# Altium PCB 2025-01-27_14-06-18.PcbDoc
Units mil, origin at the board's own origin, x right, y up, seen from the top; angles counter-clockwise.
Board outline 2000 x 2410 mil, 4 copper layers (Top Layer, MidLayer1, MidLayer2, Bottom Layer); 13 components, 6 nets, 26 pads, 90 vias.
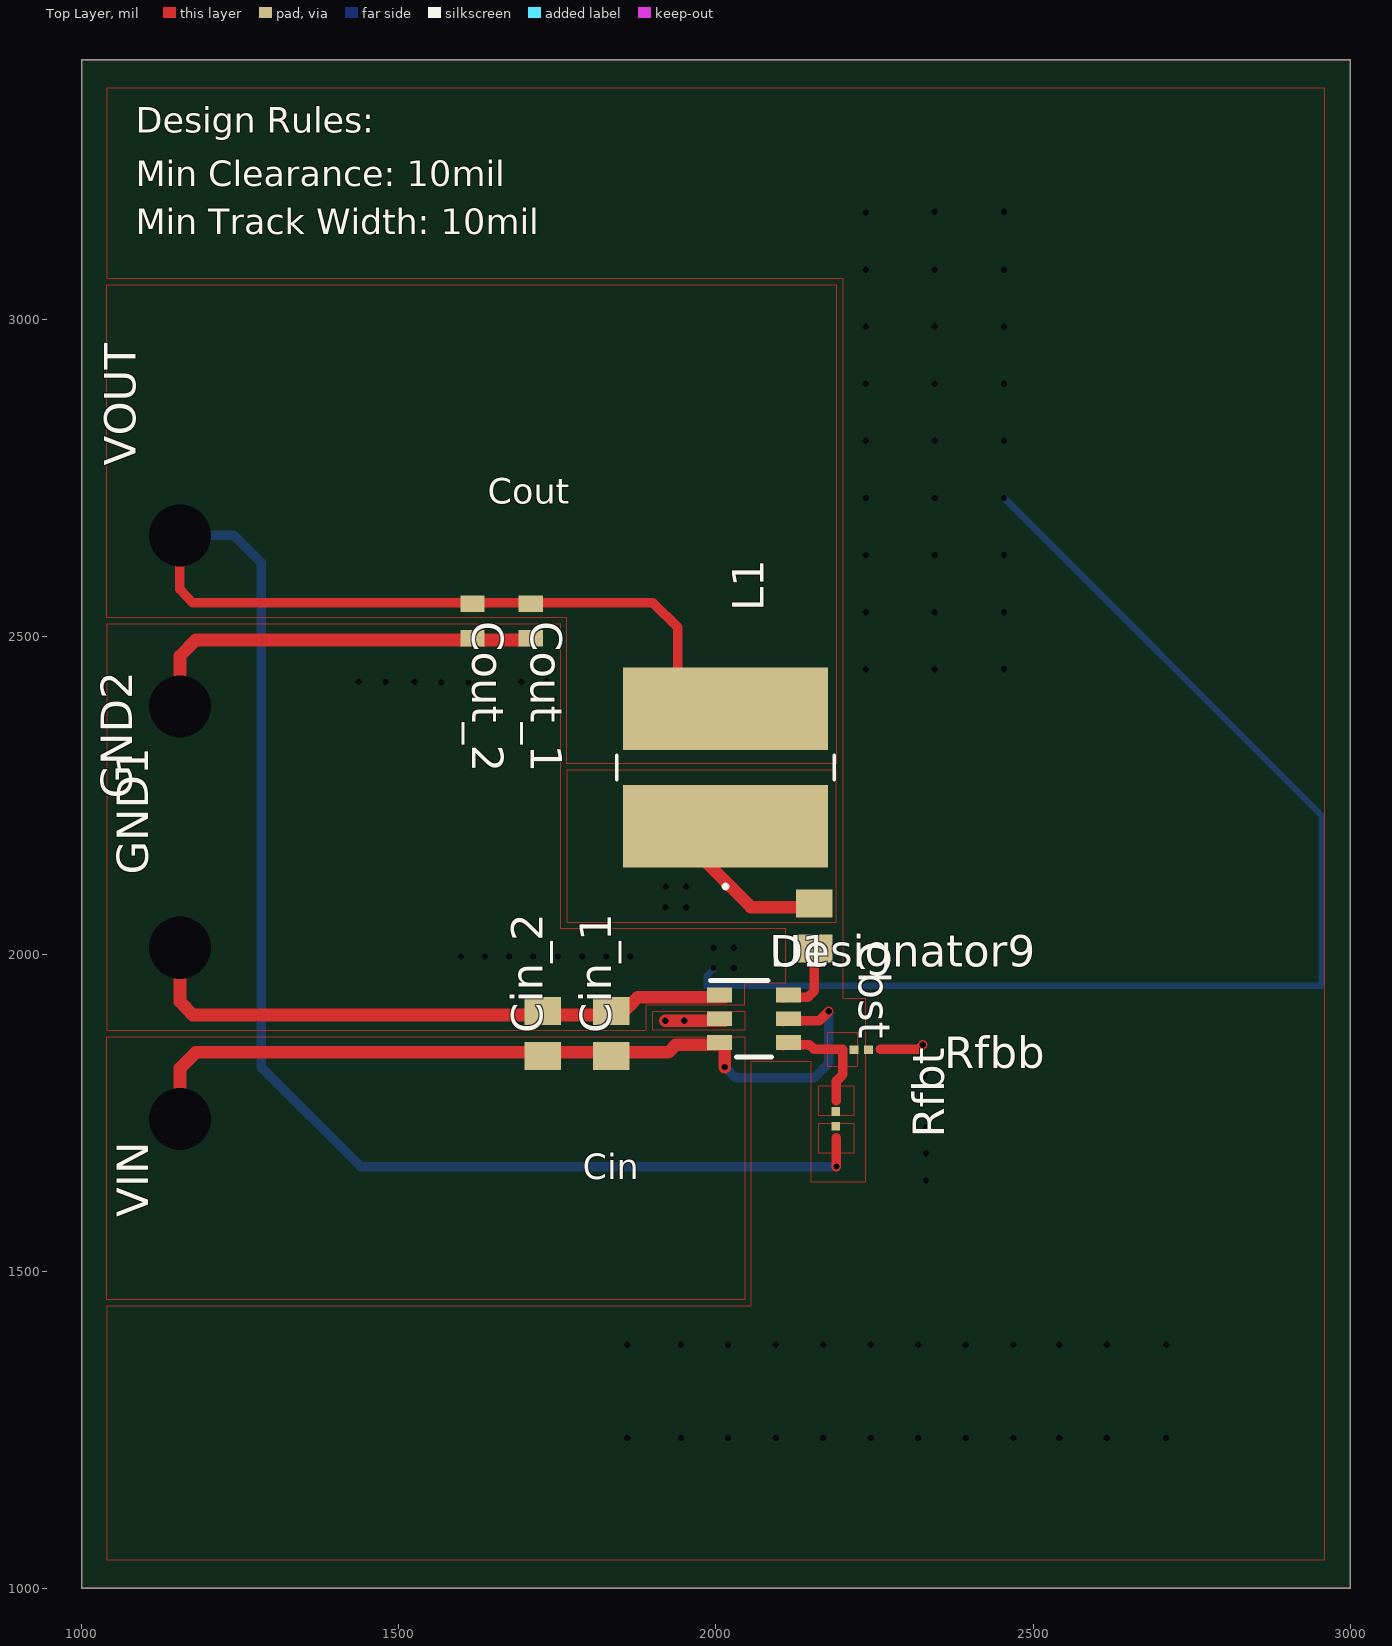
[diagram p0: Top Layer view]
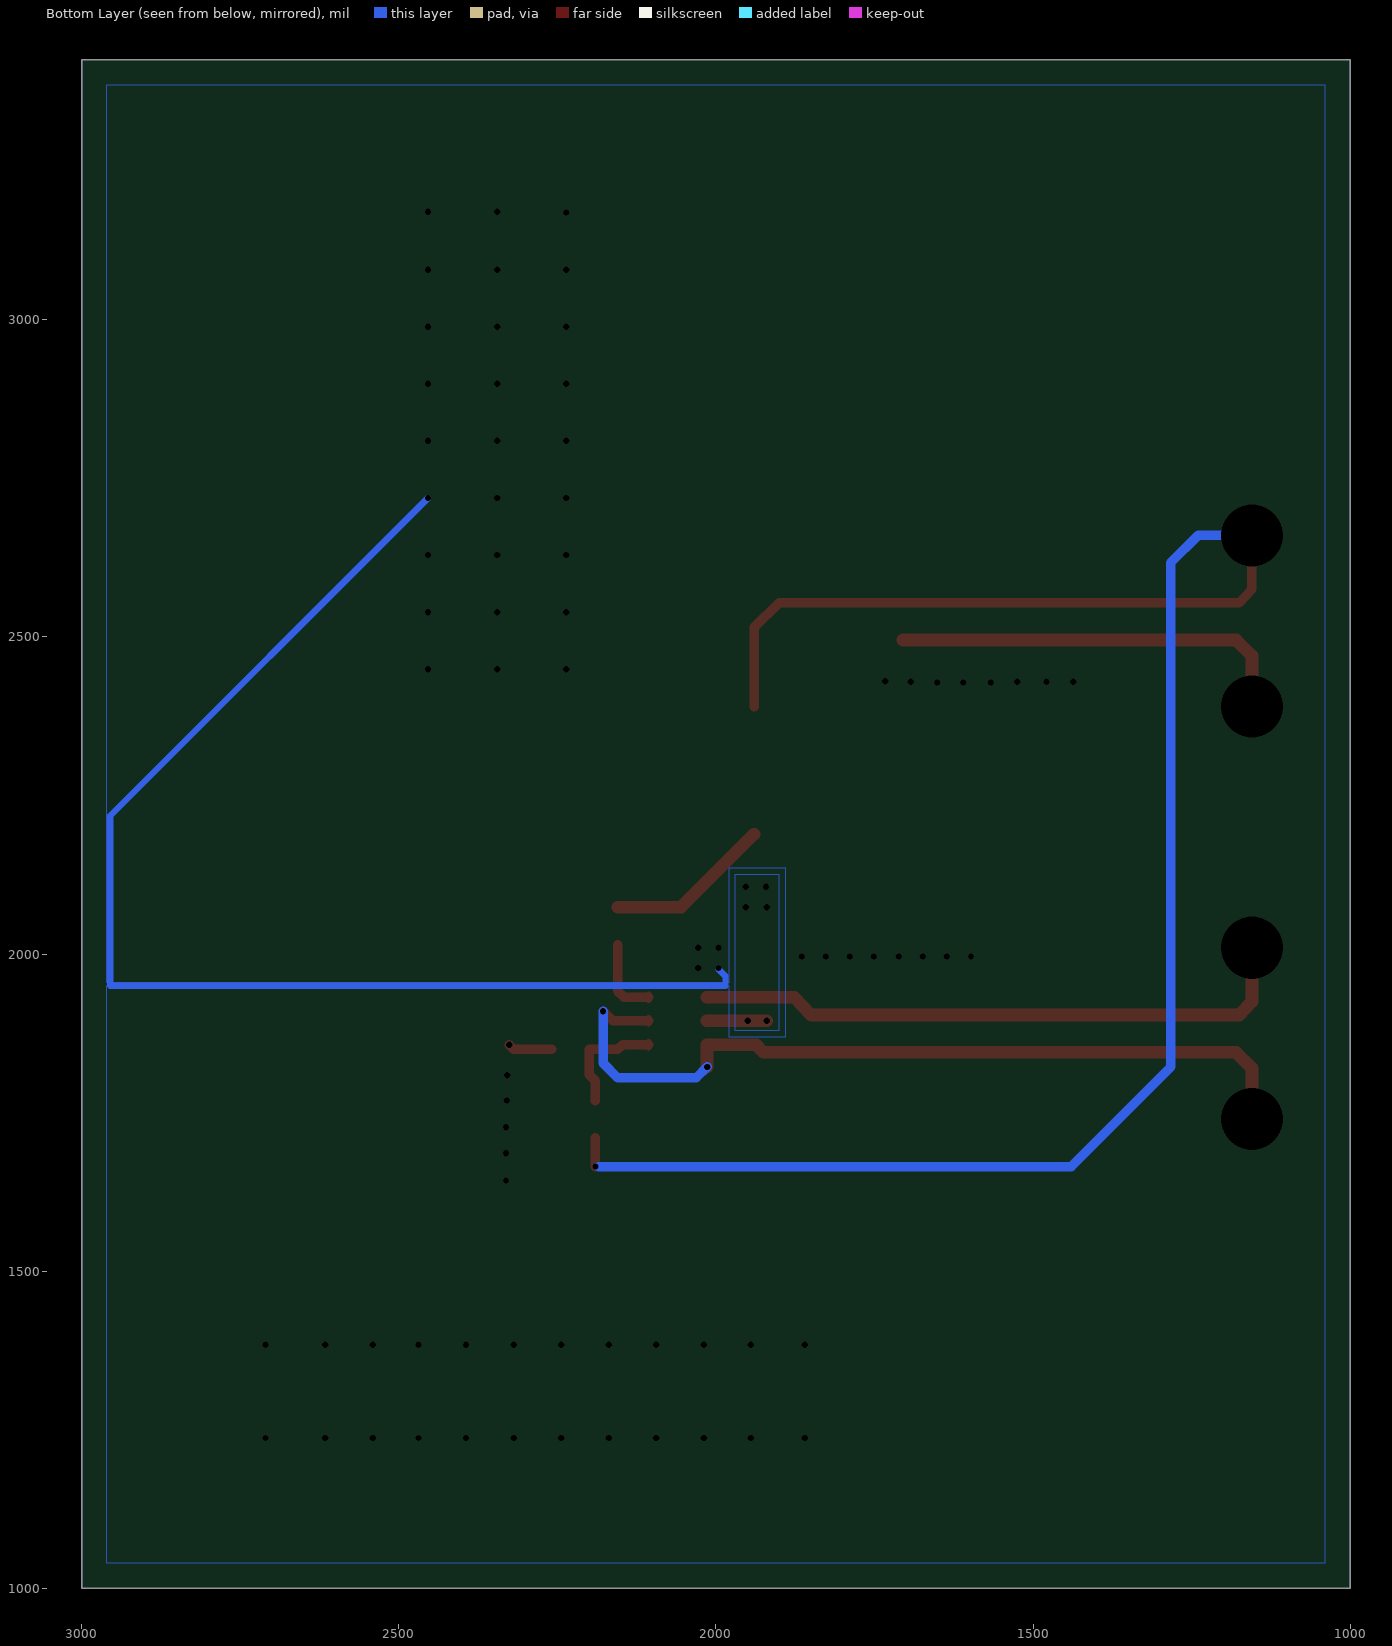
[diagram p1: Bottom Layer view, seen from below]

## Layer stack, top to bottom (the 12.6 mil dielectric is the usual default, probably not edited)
Top Layer: signal copper 1.4
Dielectric: core 12.6, FR-4, Dk 4.8
MidLayer1: signal copper 1.4
Dielectric: prepreg 12.6, FR-4, Dk 4.8
MidLayer2: signal copper 1.4
Dielectric: core 12.6, FR-4, Dk 4.8
Bottom Layer: signal copper 1.4

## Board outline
1000,1000 3000,1000 3000,3410 1000,3410

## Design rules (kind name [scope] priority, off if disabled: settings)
PlaneConnect [All] p0: scope1count=1 scope1_0_kind=Board scope1_0_value=Board scope2count=1 scope2_0_kind=Board scope2_0_value=Board commentlength=0 planeconnectstyle=Direct reliefexpansion=20 reliefentries=4 reliefconductorwidth=10 reliefairgap=10
PlaneConnect [All] p1: planeconnectstyle=Direct reliefexpansion=20 reliefentries=4 reliefconductorwidth=10 reliefairgap=10
PolygonConnect [All] p0: scope1count=1 scope1_0_kind=Board scope1_0_value=Board scope2count=1 scope2_0_kind=Board scope2_0_value=Board commentlength=0 connectstyle=Direct reliefconductorwidth=10 reliefentries=4 polygonreliefangle="90 Angle"
PolygonConnect [All] p1: connectstyle=Direct reliefconductorwidth=10 reliefentries=4 polygonreliefangle="90 Angle"

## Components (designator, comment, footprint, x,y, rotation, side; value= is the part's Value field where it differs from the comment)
Cbst "" 0805 2155,2044 r270 top
Cin_1 "" 0805 1835,1875 r90 top
Cin_2 "" 0805 1727,1875 r90 top
Cout_1 "" 0603 1708,2525 r270 top
Cout_2 "" 0603 1616,2525 r270 top
GND1 "" TP-1502 1155,2009 r90 top
GND2 "" TP-1502 1155,2389 r90 top
L1 "" VLP8040 2015,2294 r90 top
Rfbb "" 0201 2229,1849 r0 top
Rfbt "" 0201 2189,1740 r90 top
U1 "" DDC0006A_N 2060,1898 r0 top
VIN "" TP-1502 1155,1740 r90 top
VOUT "" TP-1502 1155,2659 r90 top

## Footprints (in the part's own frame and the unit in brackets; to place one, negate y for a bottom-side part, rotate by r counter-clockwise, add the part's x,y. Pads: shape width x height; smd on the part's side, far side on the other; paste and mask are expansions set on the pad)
0201 [mil]
  rect 14x13 smd: 1(-11.5,0) 2(11.5,0)
0603 [mil]
  rect 26x38 smd: 1(-27.5,0) 2(27.5,0)
0805 [mil]
  rect 44x57 smd: 1(-35.5,0) 2(35.5,0)
DDC0006A_N [mm]
  rect 1x0.6 smd: 1(-1.375,0.95) 2(-1.375,0) 3(-1.375,-0.95) 4(1.375,-0.95) 5(1.375,0) 6(1.375,0.95)
  silkscreen extent -1.75,-1.52 0.7,1.53
TP-1502 [mil]
  round 65 hole 32: 1(0,0)
VLP8040 [mil]
  rect 130x323 smd: 1(-92.5,0) 2(92.5,0)
  silkscreen extent -190,-172 19,172

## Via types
v1: diameter 0, hole 10, Top Layer to Bottom Layer, 86 vias
v2: diameter 0, hole 98, Top Layer to Bottom Layer, 4 vias

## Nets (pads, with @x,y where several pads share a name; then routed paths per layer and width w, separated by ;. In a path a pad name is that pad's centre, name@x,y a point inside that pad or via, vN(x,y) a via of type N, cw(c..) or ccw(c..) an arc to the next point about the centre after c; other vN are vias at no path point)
0: Cin_1.2 Cin_2.2 Cout_1.2 Cout_2.2 GND1.1 GND2.1 Rfbb.2 U1.1 | length 3662.2
  Top Layer w10: U1.1@2014,1928 U1.1@2014,1936
  Top Layer w15: 2259,1850 2319,1850 v1(2326,1857)
  Top Layer w20: v2(1155,2010) 1155,1925 1175,1904 1850,1904 1877,1932 U1.1@2014,1932 ; v2(1155,2390) 1155,2470 1180,2495 Cout_1.2@1705,2495
  Bottom Layer w10: v1(1996,1978) 1996,1976 1985,1965 1985,1950 2955,1950 2955,2218 v1(2454,2719)
  other v1: 1860,1237 1945,1237 2019,1237 2094,1237 2169,1237 2244,1237 2319,1237 2394,1237 2469,1237 2541,1237 2616,1237 2710,1237 1860,1384 1945,1384 2019,1384 2094,1384 2169,1384 2244,1384 2319,1384 2394,1384 2469,1384 2541,1384 2616,1384 2710,1384 2331,1643 2331,1686 2331,1727 2330,1769 2329,1809 2028,1978 1598,1996 1636,1996 1674,1996 1712,1996 1751,1996 1789,1996 1827,1996 1865,1996 1996,2010 2028,2010 1567,2428 1610,2428 1651,2428 1437,2429 1479,2429 1525,2429 1693,2429 1733,2430 2236,2449 2345,2449 2454,2449 2236,2539 2345,2539 2454,2539 2236,2629 2345,2629 2454,2629 2236,2719 2345,2719 2236,2809 2345,2809 2454,2809 2236,2899 2345,2899 2454,2899 2236,2989 2345,2989 2454,2989 2236,3079 2345,3079 2454,3079 2236,3169 2345,3170 2454,3170
1: Cin_1.1 Cin_2.1 U1.3 U1.5 VIN.1 | length 1346.1
  Top Layer w10: U1.3@2014,1853 U1.3@2014,1861 ; U1.5@2106,1891 U1.5@2106,1899
  Top Layer w15: U1.5@2106,1895 2163,1895 v1(2178,1910)
  Top Layer w20: v2(1155,1740) 1155,1820 1180,1845 1850,1845 1925,1845 1937,1857 2014,1857 v1(2014,1822)
  Bottom Layer w15: v1(2014,1822) 2031,1805 2155,1805 2178,1828 v1(2178,1910)
2: Rfbb.1 Rfbt.2 U1.4 | length 189.8
  Top Layer w10: U1.4@2106,1853 U1.4@2106,1861
  Top Layer w15: U1.4@2106,1857 2147,1857 2155,1850 2200,1850 2200,1810 2190,1800 2190,1769
4: Cbst.1 L1.1 U1.2 | length 364.6
  Top Layer w10: U1.2@2014,1891 U1.2@2014,1899
  Top Layer w20: v1(1920,1895) U1.2@2014,1895 ; L1.1@1940,2189 2055,2074 Cbst.1@2155,2074
  other v1: 1950,1895 1920,2074 1953,2074 1921,2106 1953,2106
5: Cout_1.1 Cout_2.1 L1.2 Rfbt.1 VOUT.1 | length 2972.7
  Top Layer w15: v2(1155,2660) 1155,2575 1175,2554 1705,2554 1900,2554 1940,2515 L1.2@1940,2390 ; v1(2190,1665) 2190,1710
  Bottom Layer w15: v2(1155,2660) 1240,2660 1283,2617 1283,1822 1440,1665 2185,1665
6: Cbst.2 U1.6 | length 134.1
  Top Layer w10: U1.6@2106,1928 U1.6@2106,1936
  Top Layer w15: U1.6@2106,1932 2145,1932 2155,1942 Cbst.2@2155,2015

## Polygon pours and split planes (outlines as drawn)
2 on Top Layer " " (solid, pour order 0): 2176,1822 2176,1877 2223,1877 2223,1822
2 on Top Layer " " (solid, pour order 1): 2162,1745 2162,1792 2217,1792 2217,1745
5 on Top Layer " " (solid, pour order 2): 2162,1686 2162,1733 2217,1733 2217,1686
4 on Top Layer " " (solid, pour order 4): 2190,2290 1765,2290 1765,2050 2190,2050
1 on Top Layer " " (solid, pour order 5): 1040,1870 2045,1870 2045,1455 1040,1455
5 on Top Layer " " (solid, pour order 6): 2190,2300 1765,2300 1765,2530 1040,2530 1040,3055 2190,3055
4 on Top Layer " " (solid, pour order 7): 2045,1910 2045,1880 1900,1880 1900,1910
0 on Top Layer " " (solid, pour order 9): 1040,1880 1890,1880 1890,1920 2045,1920 2045,1955 2110,1955 2110,2040 1755,2040 1755,2520 1040,2520
0 on Top Layer " " (solid, pour order 10): 1040,1445 1040,1045 2960,1045 2960,3365 1040,3365 1040,3065 2200,3065 2200,1930 2235,1930 2235,1640 2150,1640 2150,1830 2055,1830 2055,1445
4 on Bottom Layer " " (solid, pour order 3): 1900,1880 1900,2125 1970,2125 1970,1880
0 on Bottom Layer " " (solid, pour order 8): 1040,1040 2960,1040 2960,1950 1980,1950 1980,1870 1890,1870 1890,2135 1980,2135 1980,1955 2960,1955 2960,3370 1040,3370

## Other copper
Multi-Layer:
  the board outline again, w1

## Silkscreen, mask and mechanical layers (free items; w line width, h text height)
Top Overlay:
  text "Design Rules:" at 1085,3295 h40
  text "Min Clearance: 10mil" at 1085,3210 h40
  text "Min Track Width: 10mil" at 1085,3135 h40
  text "Cout" at 1640,2710 h40
  text "Cin" at 1790,1645 h40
